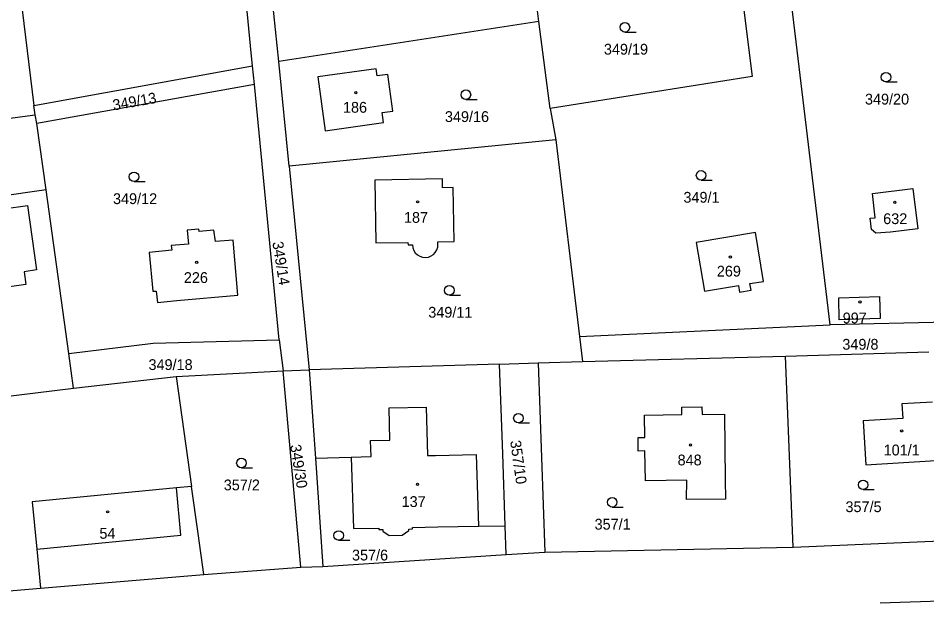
# Model space of a CAD drawing. Extents: x -725728 to -720881, y -1068679 to -1063504.
# Drawn here: x -724380.5 to -724237.4, y -1067048.9 to -1066956.8 of the extents above; entities that cross this region are included whole.
import ezdxf

# ---------------------------------------------------------------- set-up
doc = ezdxf.new("R2010")
doc.units = 0
for name, color, linetype in [('Hranice parcel', 7, 'Continuous'), ('Parcelní čísla', 7, 'Continuous'), ('Vnitřní kresba', 7, 'Continuous'), ('Značky budov', 7, 'Continuous'), ('Značky kultur', 7, 'Continuous')]:
    doc.layers.add(name, color=color, linetype=linetype)

# ---------------------------------------------------------------- blocks, each defined once
blk = doc.blocks.new('4.02_3')
at = {"layer": 'Značky budov'}
blk.add_circle((-0.001, 0), 0.0175, dxfattribs=at)
blk = doc.blocks.new('3.04_2')
at = {"layer": 'Značky kultur'}
blk.add_line((0.001, 0), (0.176, 0), dxfattribs=at)
blk.add_circle((0.001, 0.075), 0.075, dxfattribs=at)
blk = doc.blocks.new('3.04_3')
at = {"layer": 'Značky kultur'}
blk.add_line((0.001, 0), (0.176, 0), dxfattribs=at)
blk.add_circle((0.001, 0.075), 0.075, dxfattribs=at)

msp = doc.modelspace()

# ---------------------------------------------------------------- linework, layer by layer
at = {"layer": 'Hranice parcel'}
for p, q in [((-724339.48, -1066963.64), (-724341.89, -1066940.63)), ((-724252.63, -1067005.13), (-724259.36, -1066949.12)), ((-724298.49, -1066957.35), (-724299.27, -1066951.45)), ((-724298.49, -1066957.35), (-724339.48, -1066963.64)), ((-724296.75, -1066971.04), (-724298.49, -1066957.35)), ((-724378.07, -1066970.58), (-724343.63, -1066964.33)), ((-724337.85, -1066980.12), (-724339.48, -1066963.64)), ((-724343.33, -1066967.31), (-724377.6, -1066973.43)), ((-724339.44, -1067007.48), (-724343.33, -1066967.31)), ((-724377.89, -1066972.07), (-724378.07, -1066970.58)), ((-724296.75, -1066971.04), (-724295.84, -1066975.98)), ((-724415.58, -1066977.07), (-724377.89, -1066972.07)), ((-724377.6, -1066973.43), (-724377.89, -1066972.07)), ((-724376.14, -1066983.89), (-724377.6, -1066973.43)), ((-724295.84, -1066975.98), (-724337.85, -1066980.12)), ((-724295.84, -1066975.98), (-724292.12, -1067006.94)), ((-724337.85, -1066980.12), (-724334.69, -1067012.18)), ((-724372.55, -1067009.65), (-724376.14, -1066983.89)), ((-724232.02, -1067004.64), (-724252.63, -1067005.13)), ((-724292.12, -1067006.94), (-724252.63, -1067005.13)), ((-724339.44, -1067007.48), (-724338.81, -1067012.38)), ((-724292.12, -1067006.94), (-724291.61, -1067010.91)), ((-724371.8, -1067015.06), (-724372.55, -1067009.65)), ((-724291.61, -1067010.91), (-724259.66, -1067010.04)), ((-724259.66, -1067010.04), (-724237.05, -1067009.35)), ((-724258.46, -1067040.09), (-724259.66, -1067010.04)), ((-724304.7, -1067011.3), (-724334.69, -1067012.18)), ((-724304.7, -1067011.3), (-724298.63, -1067011.12)), ((-724298.63, -1067011.12), (-724291.61, -1067010.91)), ((-724298.63, -1067011.12), (-724297.58, -1067040.88)), ((-724371.8, -1067015.06), (-724355.65, -1067013.26)), ((-724355.65, -1067013.26), (-724338.81, -1067012.38)), ((-724355.65, -1067013.26), (-724353.22, -1067030.55)), ((-724338.81, -1067012.38), (-724334.69, -1067012.18)), ((-724336.03, -1067043.28), (-724338.81, -1067012.38)), ((-724334.69, -1067012.18), (-724333.72, -1067026.11)), ((-724386.74, -1067016.93), (-724371.8, -1067015.06)), ((-724333.72, -1067026.11), (-724332.54, -1067043.14)), ((-724303.64, -1067041.27), (-724303.8, -1067036.75)), ((-724258.46, -1067040.09), (-724235.21, -1067039.14)), ((-724297.58, -1067040.88), (-724258.46, -1067040.09)), ((-724332.54, -1067043.14), (-724303.64, -1067041.27)), ((-724303.64, -1067041.27), (-724297.58, -1067040.88)), ((-724351.28, -1067044.43), (-724336.03, -1067043.28)), ((-724336.03, -1067043.28), (-724332.54, -1067043.14)), ((-724377.02, -1067046.58), (-724351.28, -1067044.43)), ((-724396.36, -1067048.2), (-724377.02, -1067046.58))]:
    msp.add_line(p, q, dxfattribs=at)
for points in [[(-724382.56, -1066933.86), (-724380.98, -1066946.86), (-724378.07, -1066970.58)], [(-724266.89, -1066950.08), (-724264.91, -1066966.01), (-724296.75, -1066971.04)], [(-724343.63, -1066964.33), (-724343.77, -1066962.83), (-724344.71, -1066952.98)], [(-724343.33, -1066967.31), (-724343.48, -1066965.82), (-724343.63, -1066964.33)], [(-724332.16, -1066974.56), (-724322.96, -1066973.29), (-724323.18, -1066971.7), (-724321.49, -1066971.46), (-724322.29, -1066965.69), (-724323.98, -1066965.92), (-724324.13, -1066964.83), (-724333.34, -1066966.1), (-724332.16, -1066974.56)], [(-724314.4, -1066992.46), (-724314.4, -1066992.06), (-724311.84, -1066992.02), (-724312.02, -1066983.51), (-724313.69, -1066983.53), (-724313.7, -1066982.15), (-724324.36, -1066982.32), (-724324.2, -1066992.21), (-724319.13, -1066992.14), (-724319.12, -1066992.53), (-724318.42, -1066992.52)], [(-724376.14, -1066983.89), (-724391.87, -1066986.12), (-724386.74, -1067016.93)], [(-724246.11, -1066990.12), (-724246.33, -1066988.35), (-724245.52, -1066988.27), (-724245.97, -1066984.46), (-724239.6, -1066983.67), (-724238.8, -1066989.98), (-724243.1, -1066990.53), (-724245.42, -1066990.68), (-724246.11, -1066990.12)], [(-724345.92, -1067000.45), (-724346.65, -1066991.79), (-724349.43, -1066992.02), (-724349.74, -1066990.23), (-724352.04, -1066990.44), (-724352.08, -1066990.05), (-724353.91, -1066990.21), (-724353.73, -1066992.43), (-724356.42, -1066992.64), (-724356.34, -1066993.38), (-724359.89, -1066993.73), (-724359.35, -1066999.82), (-724358.8, -1066999.8), (-724358.6, -1067001.59), (-724355.57, -1067001.26), (-724345.92, -1067000.45)], [(-724263.1, -1066998.27), (-724264.38, -1066990.58), (-724273.7, -1066992.13), (-724272.41, -1066999.83), (-724267.07, -1066998.94), (-724266.9, -1066999.96), (-724265.08, -1066999.66), (-724265.26, -1066998.63), (-724263.1, -1066998.27)], [(-724318.42, -1066992.52), (-724318.36, -1066992.97), (-724318.21, -1066993.39), (-724317.97, -1066993.76), (-724317.65, -1066994.08), (-724317.26, -1066994.31), (-724316.84, -1066994.45), (-724316.81, -1066994.46), (-724316.37, -1066994.5), (-724315.92, -1066994.44), (-724315.5, -1066994.28), (-724315.13, -1066994.04), (-724314.82, -1066993.72), (-724314.59, -1066993.33), (-724314.44, -1066992.91), (-724314.4, -1066992.46)], [(-724244.71, -1067004.1), (-724251.17, -1067004.34), (-724251.26, -1067000.88), (-724244.84, -1067000.67), (-724244.71, -1067004.1)], [(-724372.55, -1067009.65), (-724359.27, -1067007.99), (-724339.44, -1067007.48)], [(-724303.8, -1067036.75), (-724304.2, -1067025.4), (-724304.7, -1067011.3)], [(-724236.5, -1067017.28), (-724241.3, -1067017.57), (-724241.15, -1067019.87), (-724247.39, -1067020.25), (-724246.97, -1067027.14), (-724235.99, -1067026.47)], [(-724281.79, -1067024.97), (-724282.85, -1067024.99), (-724282.88, -1067022.85), (-724281.83, -1067022.83), (-724281.87, -1067019.33), (-724275.96, -1067019.25), (-724275.98, -1067018.08), (-724272.81, -1067018.04), (-724272.8, -1067019.21), (-724269.25, -1067019.16), (-724269.15, -1067029.53), (-724269.11, -1067032.57), (-724275.23, -1067032.63), (-724275.22, -1067029.59), (-724281.73, -1067029.66), (-724281.79, -1067024.97)], [(-724333.72, -1067026.11), (-724328.1, -1067025.95), (-724327.7, -1067037.17), (-724323.71, -1067037.1), (-724323.71, -1067037.35), (-724323.11, -1067037.34), (-724323.1, -1067037.59), (-724322.07, -1067038.27), (-724320.02, -1067038.21), (-724319.02, -1067037.51), (-724319.02, -1067037.26), (-724318.42, -1067037.25), (-724318.43, -1067037), (-724314.44, -1067036.93), (-724308.01, -1067036.82), (-724303.8, -1067036.75)], [(-724353.22, -1067030.55), (-724355.61, -1067030.78), (-724378.33, -1067032.97), (-724377.61, -1067040.43), (-724377.02, -1067046.58)], [(-724351.28, -1067044.43), (-724352.18, -1067037.98), (-724353.22, -1067030.55)], [(-724223.6, -1067044.73), (-724230.84, -1067047.46), (-724233.67, -1067048.56), (-724244.76, -1067048.93)]]:
    msp.add_lwpolyline(points, dxfattribs=at)
at = {"layer": 'Vnitřní kresba'}
for p, q in [((-724382.81, -1066986.86), (-724379.07, -1066986.33)), ((-724379.07, -1066986.33), (-724377.63, -1066996.47)), ((-724377.63, -1066996.47), (-724379.62, -1066996.76)), ((-724379.62, -1066996.76), (-724379.34, -1066998.75)), ((-724379.34, -1066998.75), (-724384.41, -1066999.46)), ((-724322.08, -1067018.19), (-724316.24, -1067018.07)), ((-724322, -1067023.25), (-724322.08, -1067018.19)), ((-724316.24, -1067018.07), (-724316.04, -1067025.66)), ((-724325.01, -1067023.3), (-724322, -1067023.25)), ((-724324.95, -1067025.86), (-724325.01, -1067023.3)), ((-724328.1, -1067025.95), (-724324.95, -1067025.86)), ((-724316.04, -1067025.66), (-724314.79, -1067025.68)), ((-724314.79, -1067025.68), (-724308.37, -1067025.51)), ((-724308.37, -1067025.51), (-724308.01, -1067036.82)), ((-724354.89, -1067038.24), (-724355.61, -1067030.78)), ((-724377.61, -1067040.43), (-724354.89, -1067038.24))]:
    msp.add_line(p, q, dxfattribs=at)

# ---------------------------------------------------------------- block references
at = {"layer": 'Značky budov', "xscale": 10, "yscale": 10}
for p in [(-724327.33, -1066968.56), (-724317.6, -1066985.76), (-724242.42, -1066985.85), (-724268.32, -1066994.44), (-724352.4, -1066995.27), (-724247.92, -1067001.52), (-724241.33, -1067021.81), (-724274.61, -1067024.03), (-724317.62, -1067030.24), (-724366.44, -1067034.55)]:
    msp.add_blockref('4.02_3', p, dxfattribs=at)
at = {"layer": 'Značky kultur', "xscale": 10, "yscale": 10}
for name, p in [('3.04_2', (-724284.96, -1066959.03)), ('3.04_3', (-724243.83, -1066966.89)), ('3.04_3', (-724310.01, -1066969.64)), ('3.04_2', (-724362.3, -1066982.56)), ('3.04_2', (-724272.96, -1066982.34)), ('3.04_2', (-724312.62, -1067000.44)), ('3.04_2', (-724301.74, -1067020.56)), ('3.04_2', (-724345.38, -1067027.62)), ('3.04_2', (-724247.43, -1067031.05)), ('3.04_2', (-724286.96, -1067033.8)), ('3.04_2', (-724330.06, -1067039.03))]:
    msp.add_blockref(name, p, dxfattribs=at)

# ---------------------------------------------------------------- texts
at = {"layer": 'Parcelní čísla'}
for s, p in [('349/19', (-724288.26, -1066962.58)), ('349/20', (-724247.13, -1066970.44)), ('186', (-724329.37, -1066971.73)), ('349/16', (-724313.31, -1066973.19)), ('349/12', (-724365.6, -1066986.11)), ('349/1', (-724275.73, -1066985.89)), ('187', (-724319.76, -1066989.06)), ('632', (-724244.26, -1066989.26)), ('269', (-724270.47, -1066997.52)), ('226', (-724354.44, -1066998.53)), ('349/11', (-724315.93, -1067003.99)), ('997', (-724250.64, -1067004.89)), ('349/8', (-724250.69, -1067009.03)), ('349/18', (-724360.01, -1067012.23)), ('101/1', (-724244.19, -1067025.67)), ('848', (-724276.65, -1067027.24)), ('357/2', (-724348.15, -1067031.17)), ('137', (-724320.13, -1067033.79)), ('357/5', (-724250.2, -1067034.6)), ('357/1', (-724289.73, -1067037.35)), ('54', (-724367.74, -1067038.79)), ('357/6', (-724327.95, -1067042.21))]:
    msp.add_text(s, height=1.7, dxfattribs=at).set_placement(p)
for s, rotation, p in [('349/13', 10, (-724365.5, -1066971.38)), ('349/14', 279, (-724340.5, -1066992.13)), ('357/10', 278, (-724303.04, -1067023.41)), ('349/30', 279, (-724337.7, -1067024.08))]:
    msp.add_text(s, height=1.7, rotation=rotation, dxfattribs=at).set_placement(p)

doc.saveas('drawing.dxf')
